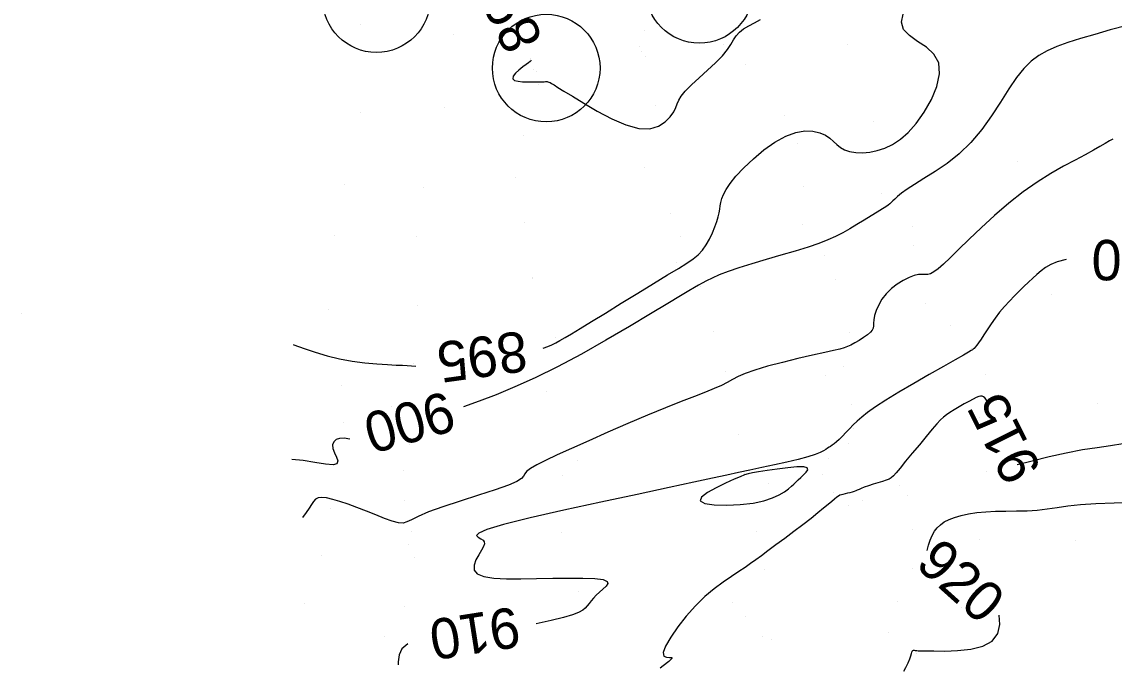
# Model space of a CAD drawing. Extents: x 400243 to 403697, y 4403637 to 4408083.
# Drawn here: x 402504.4 to 402707.4, y 4405858.2 to 4405978.9 of the extents above; entities that cross this region are included whole.
import ezdxf

# ---------------------------------------------------------------- set-up
doc = ezdxf.new("R2010")
doc.units = 0
for name, color, linetype in [('HH_DiS', 7, 'Continuous'), ('HH_IC', 7, 'Continuous'), ('SNR_ONAMA', 7, 'Continuous')]:
    doc.layers.add(name, color=color, linetype=linetype)

msp = doc.modelspace()

# ---------------------------------------------------------------- linework, layer by layer
at = {"layer": 'HH_DiS'}
msp.add_line((402504.4, 4405924.73), (402504.4, 4405924.73), dxfattribs=at)
at = {"layer": 'HH_IC'}
for p, q in [((402567.41, 4405978.32), (402567.41, 4405978.32)), ((402599.72, 4405977.73), (402599.72, 4405977.73)), ((402620.1, 4405977.21), (402620.1, 4405977.21)), ((402584.66, 4405976.5), (402584.66, 4405976.5)), ((402619.26, 4405974.35), (402619.26, 4405974.35)), ((402619.63, 4405973.41), (402619.63, 4405973.41)), ((402634.75, 4405974.66), (402634.75, 4405974.66)), ((402657.86, 4405974.74), (402657.86, 4405974.74)), ((402598.88, 4405972), (402598.88, 4405972)), ((402620.2, 4405972.39), (402620.2, 4405972.39)), ((402638.88, 4405970.91), (402638.88, 4405970.91)), ((402599.47, 4405970.08), (402599.47, 4405970.08)), ((402600.09, 4405969.61), (402600.09, 4405969.61)), ((402600.34, 4405967.28), (402600.34, 4405967.28)), ((402582.89, 4405963.02), (402582.89, 4405963.02)), ((402622.14, 4405963.27), (402622.14, 4405963.27)), ((402567.32, 4405961.95), (402567.32, 4405961.95)), ((402646.13, 4405961.54), (402646.13, 4405961.54)), ((402662.57, 4405960.36), (402662.57, 4405960.36)), ((402597.54, 4405957.69), (402597.54, 4405957.69)), ((402648.47, 4405956.34), (402648.47, 4405956.34)), ((402689.48, 4405952.9), (402689.48, 4405952.9)), ((402620.08, 4405951.86), (402620.08, 4405951.86)), ((402564.33, 4405948.7), (402564.33, 4405948.7)), ((402596.16, 4405950), (402596.16, 4405950)), ((402579.05, 4405948.12), (402579.05, 4405948.12)), ((402649.67, 4405948.24), (402649.67, 4405948.24)), ((402664.22, 4405946.92), (402664.22, 4405946.92)), ((402624.85, 4405943.23), (402624.85, 4405943.23)), ((402597.74, 4405941.59), (402597.74, 4405941.59)), ((402649.48, 4405941.23), (402649.48, 4405941.23)), ((402669.95, 4405940.82), (402669.95, 4405940.82)), ((402562.58, 4405939.24), (402562.58, 4405939.24)), ((402577.72, 4405938.95), (402577.72, 4405938.95)), ((402626.84, 4405939.04), (402626.84, 4405939.04)), ((402670.1, 4405937.33), (402670.1, 4405937.33)), ((402653.55, 4405935.46), (402653.55, 4405935.46)), ((402626.13, 4405934.15), (402626.13, 4405934.15)), ((402599.3, 4405931.25), (402599.3, 4405931.25)), ((402599.31, 4405931.33), (402599.31, 4405931.33)), ((402655.68, 4405931.05), (402655.68, 4405931.05)), ((402630.43, 4405929.66), (402630.43, 4405929.66)), ((402695.72, 4405928.13), (402695.72, 4405928.13)), ((402578.01, 4405926.16), (402578.01, 4405926.16)), ((402672.32, 4405926.46), (402672.32, 4405926.46)), ((402561.38, 4405925.37), (402561.38, 4405925.37)), ((402676.98, 4405922.5), (402676.98, 4405922.5)), ((402603.54, 4405920.14), (402603.54, 4405920.14)), ((402632.92, 4405921.41), (402632.92, 4405921.41)), ((402658.21, 4405921.16), (402658.21, 4405921.16)), ((402680.86, 4405918.12), (402680.86, 4405918.12)), ((402577.21, 4405915.37), (402577.21, 4405915.37)), ((402635.07, 4405913.98), (402635.07, 4405913.98)), ((402657.08, 4405914.74), (402657.08, 4405914.74)), ((402653.68, 4405913.16), (402653.68, 4405913.16)), ((402683.55, 4405913.25), (402683.55, 4405913.25)), ((402563.78, 4405911.26), (402563.78, 4405911.26)), ((402601.94, 4405910.25), (402601.94, 4405910.25)), ((402685.86, 4405909.63), (402685.86, 4405909.63)), ((402704.22, 4405907.86), (402704.22, 4405907.86)), ((402573.05, 4405907.42), (402573.05, 4405907.42)), ((402658.56, 4405907.74), (402658.56, 4405907.74)), ((402564.26, 4405904.35), (402564.26, 4405904.35)), ((402573.53, 4405904.11), (402573.53, 4405904.11)), ((402682.44, 4405905.31), (402682.44, 4405905.31)), ((402637.59, 4405902.25), (402637.59, 4405902.25)), ((402658.97, 4405903.37), (402658.97, 4405903.37)), ((402576.46, 4405900.32), (402576.46, 4405900.32)), ((402657.93, 4405900.57), (402657.93, 4405900.57)), ((402654.32, 4405897.76), (402654.32, 4405897.76)), ((402607.61, 4405897.36), (402607.61, 4405897.36)), ((402575.39, 4405895.54), (402575.39, 4405895.54)), ((402604.91, 4405894.63), (402604.91, 4405894.63)), ((402638.71, 4405894.99), (402638.71, 4405894.99)), ((402653.26, 4405894.7), (402653.26, 4405894.7)), ((402683.59, 4405895.37), (402683.59, 4405895.37)), ((402643.21, 4405893.04), (402643.21, 4405893.04)), ((402667.46, 4405892.72), (402667.46, 4405892.72)), ((402575.54, 4405889.88), (402575.54, 4405889.88)), ((402655.18, 4405891.41), (402655.18, 4405891.41)), ((402660.66, 4405890), (402660.66, 4405890)), ((402668.94, 4405890.8), (402668.94, 4405890.8)), ((402561.84, 4405888.47), (402561.84, 4405888.47)), ((402657.98, 4405888.93), (402657.98, 4405888.93)), ((402576.83, 4405884.1), (402576.83, 4405884.1)), ((402604.75, 4405883.93), (402604.75, 4405883.93)), ((402640.98, 4405884.13), (402640.98, 4405884.13)), ((402669.84, 4405884.49), (402669.84, 4405884.49)), ((402576.25, 4405881.73), (402576.25, 4405881.73)), ((402682.37, 4405882.6), (402682.37, 4405882.6)), ((402700.26, 4405882.55), (402700.26, 4405882.55)), ((402560.17, 4405879.63), (402560.17, 4405879.63)), ((402577.32, 4405879.31), (402577.32, 4405879.31)), ((402669.98, 4405877.33), (402669.98, 4405877.33)), ((402642.42, 4405877.11), (402642.42, 4405877.11)), ((402677.56, 4405874.28), (402677.56, 4405874.28)), ((402607.77, 4405873.07), (402607.77, 4405873.07)), ((402556.95, 4405870.74), (402556.95, 4405870.74)), ((402575.45, 4405870.23), (402575.45, 4405870.23)), ((402636.42, 4405870.91), (402636.42, 4405870.91)), ((402667.2, 4405871.12), (402667.2, 4405871.12)), ((402679, 4405870.04), (402679, 4405870.04)), ((402638.86, 4405868.37), (402638.86, 4405868.37)), ((402665.36, 4405865.47), (402665.36, 4405865.47)), ((402571.72, 4405864.59), (402571.72, 4405864.59)), ((402641.96, 4405864.69), (402641.96, 4405864.69)), ((402643.76, 4405864.07), (402643.76, 4405864.07)), ((402670.74, 4405861.47), (402670.74, 4405861.47))]:
    msp.add_line(p, q, dxfattribs=at)
for points in [[(402599.06, 4405971.76), (402598.99, 4405971.63), (402598.84, 4405971.49), (402598.56, 4405971.28), (402598.11, 4405970.96), (402597.48, 4405970.49), (402596.78, 4405969.92), (402596.14, 4405969.32), (402595.71, 4405968.76), (402595.61, 4405968.3), (402595.94, 4405967.99), (402596.6, 4405967.82), (402597.45, 4405967.75), (402598.33, 4405967.74), (402599.1, 4405967.75), (402599.65, 4405967.75), (402600.01, 4405967.75), (402600.23, 4405967.74), (402600.39, 4405967.73), (402600.54, 4405967.73), (402600.74, 4405967.73), (402600.97, 4405967.73), (402601.23, 4405967.74), (402601.47, 4405967.75), (402601.69, 4405967.76), (402601.87, 4405967.77), (402602.03, 4405967.76), (402602.17, 4405967.73), (402602.34, 4405967.67), (402602.56, 4405967.57), (402602.85, 4405967.42), (402603.3, 4405967.15), (402604.03, 4405966.7), (402605.14, 4405966.02), (402606.73, 4405965.03), (402608.84, 4405963.73), (402611.33, 4405962.27), (402614.01, 4405960.87), (402616.65, 4405959.73), (402619.06, 4405959.06), (402621.09, 4405959.02), (402622.71, 4405959.48), (402623.97, 4405960.27), (402624.9, 4405961.22), (402625.53, 4405962.16), (402625.92, 4405962.96), (402626.18, 4405963.65), (402626.47, 4405964.33), (402626.93, 4405965.09), (402627.69, 4405966.01), (402628.84, 4405967.16), (402630.28, 4405968.48), (402631.83, 4405969.88), (402633.32, 4405971.27), (402634.59, 4405972.57), (402635.51, 4405973.71), (402636.16, 4405974.68), (402636.67, 4405975.53), (402637.16, 4405976.28), (402637.75, 4405976.94), (402638.53, 4405977.55), (402639.48, 4405978.13), (402640.54, 4405978.71), (402641.67, 4405979.31)], [(402601.27, 4405918.2), (402602.14, 4405918.54), (402602.89, 4405918.87), (402603.61, 4405919.22), (402604.39, 4405919.64), (402605.34, 4405920.18), (402606.56, 4405920.91), (402608.15, 4405921.88), (402610.23, 4405923.16), (402612.83, 4405924.76), (402615.77, 4405926.58), (402618.84, 4405928.47), (402621.78, 4405930.27), (402624.36, 4405931.84), (402626.41, 4405933.06), (402627.98, 4405934.02), (402629.17, 4405934.83), (402630.1, 4405935.59), (402630.86, 4405936.42), (402631.56, 4405937.41), (402632.18, 4405938.51), (402632.73, 4405939.65), (402633.19, 4405940.76), (402633.55, 4405941.78), (402633.8, 4405942.65), (402633.97, 4405943.39), (402634.08, 4405944.05), (402634.18, 4405944.68), (402634.3, 4405945.32), (402634.47, 4405946.02), (402634.76, 4405946.81), (402635.25, 4405947.73), (402636, 4405948.84), (402637.1, 4405950.18), (402638.57, 4405951.74), (402640.35, 4405953.42), (402642.31, 4405955.06), (402644.34, 4405956.52), (402646.34, 4405957.64), (402648.2, 4405958.32), (402649.88, 4405958.59), (402651.38, 4405958.54), (402652.66, 4405958.25), (402653.72, 4405957.79), (402654.56, 4405957.24), (402655.24, 4405956.66), (402655.85, 4405956.08), (402656.5, 4405955.54), (402657.27, 4405955.09), (402658.22, 4405954.77), (402659.35, 4405954.59), (402660.61, 4405954.55), (402661.96, 4405954.67), (402663.36, 4405954.94), (402664.78, 4405955.4), (402666.21, 4405956.08), (402667.66, 4405957.04), (402669.12, 4405958.33), (402670.6, 4405960.01), (402672.08, 4405962.09), (402673.41, 4405964.44), (402674.42, 4405966.87), (402674.94, 4405969.19), (402674.8, 4405971.23), (402673.9, 4405972.85), (402672.48, 4405974.15), (402670.86, 4405975.25), (402669.35, 4405976.31), (402668.26, 4405977.46), (402667.87, 4405978.81), (402668.17, 4405980.32)], [(402709.77, 4405978.22), (402706.64, 4405977.36), (402703.76, 4405976.54), (402701.14, 4405975.77), (402698.79, 4405975.01), (402696.72, 4405974.27), (402694.93, 4405973.5), (402693.37, 4405972.63), (402691.95, 4405971.57), (402690.59, 4405970.23), (402689.24, 4405968.52), (402687.81, 4405966.4), (402686.27, 4405963.97), (402684.6, 4405961.4), (402682.77, 4405958.84), (402680.77, 4405956.45), (402678.58, 4405954.36), (402676.32, 4405952.57), (402674.09, 4405951.04), (402672.03, 4405949.75), (402670.27, 4405948.67), (402668.89, 4405947.76), (402667.86, 4405947.02), (402667.12, 4405946.42), (402666.6, 4405945.94), (402666.24, 4405945.58), (402665.97, 4405945.31), (402665.72, 4405945.07), (402665.41, 4405944.83), (402664.96, 4405944.52), (402664.3, 4405944.1), (402663.37, 4405943.51), (402662.22, 4405942.8), (402660.94, 4405942.02), (402659.58, 4405941.21), (402658.23, 4405940.42), (402656.94, 4405939.69), (402655.62, 4405939.01), (402654.17, 4405938.35), (402652.5, 4405937.69), (402650.5, 4405937), (402648.11, 4405936.26), (402645.46, 4405935.49), (402642.71, 4405934.7), (402640.06, 4405933.93), (402637.65, 4405933.18), (402635.64, 4405932.48), (402634.01, 4405931.84), (402632.69, 4405931.26), (402631.65, 4405930.75), (402630.83, 4405930.31), (402630.14, 4405929.93), (402629.39, 4405929.5), (402628.34, 4405928.88), (402626.78, 4405927.93), (402624.46, 4405926.52), (402621.24, 4405924.58), (402617.31, 4405922.24), (402612.94, 4405919.69), (402608.39, 4405917.13), (402603.93, 4405914.76), (402599.79, 4405912.72), (402595.99, 4405911.01), (402592.52, 4405909.58), (402589.36, 4405908.36), (402586.48, 4405907.31)], [(402707.11, 4405957.08), (402706.49, 4405956.73), (402705.72, 4405956.27), (402704.74, 4405955.69), (402703.51, 4405955), (402701.98, 4405954.17), (402700.12, 4405953.19), (402697.97, 4405952.04), (402695.6, 4405950.69), (402693.07, 4405949.1), (402690.44, 4405947.26), (402687.78, 4405945.15), (402685.17, 4405942.89), (402682.69, 4405940.61), (402680.43, 4405938.46), (402678.48, 4405936.56), (402676.9, 4405935.02), (402675.65, 4405933.84), (402674.67, 4405932.99), (402673.9, 4405932.41), (402673.27, 4405932.07), (402672.73, 4405931.92), (402672.21, 4405931.9), (402671.66, 4405931.92), (402671.02, 4405931.89), (402670.24, 4405931.73), (402669.28, 4405931.37), (402668.2, 4405930.83), (402667.07, 4405930.13), (402665.99, 4405929.29), (402665.02, 4405928.35), (402664.23, 4405927.32), (402663.62, 4405926.26), (402663.17, 4405925.23), (402662.87, 4405924.29), (402662.71, 4405923.48), (402662.65, 4405922.85), (402662.64, 4405922.36), (402662.6, 4405921.95), (402662.44, 4405921.57), (402662.11, 4405921.17), (402661.54, 4405920.69), (402660.81, 4405920.18), (402659.98, 4405919.66), (402659.16, 4405919.19), (402658.42, 4405918.8), (402657.8, 4405918.51), (402657.19, 4405918.29), (402656.39, 4405918.07), (402655.25, 4405917.81), (402653.59, 4405917.44), (402651.3, 4405916.92), (402648.59, 4405916.29), (402645.72, 4405915.59), (402642.97, 4405914.86), (402640.6, 4405914.16), (402638.81, 4405913.53), (402637.48, 4405912.94), (402636.43, 4405912.39), (402635.47, 4405911.85), (402634.41, 4405911.29), (402633.08, 4405910.71), (402631.42, 4405910.05), (402629.38, 4405909.26), (402626.93, 4405908.31), (402624.02, 4405907.15), (402620.66, 4405905.76), (402617.02, 4405904.21), (402613.31, 4405902.6), (402609.74, 4405901.03), (402606.53, 4405899.6), (402603.85, 4405898.38), (402601.71, 4405897.37), (402600.08, 4405896.54), (402598.92, 4405895.86), (402598.2, 4405895.31), (402597.85, 4405894.86), (402597.63, 4405894.44), (402597.24, 4405894), (402596.41, 4405893.47), (402594.84, 4405892.79), (402592.36, 4405891.91), (402589.24, 4405890.89), (402585.88, 4405889.82), (402582.66, 4405888.75), (402579.96, 4405887.78), (402578.06, 4405886.96), (402576.81, 4405886.34), (402575.96, 4405885.92), (402575.24, 4405885.73), (402574.4, 4405885.78), (402573.24, 4405886.09), (402571.79, 4405886.6), (402570.15, 4405887.23), (402568.42, 4405887.92), (402566.68, 4405888.6), (402565.04, 4405889.21), (402563.52, 4405889.73), (402562.18, 4405890.12), (402561.03, 4405890.38), (402560.12, 4405890.47), (402559.45, 4405890.39), (402558.97, 4405890.14), (402558.6, 4405889.74), (402558.24, 4405889.18), (402557.81, 4405888.49), (402557.25, 4405887.68), (402556.58, 4405886.75)], [(402698.47, 4405934.68), (402696.78, 4405934.27), (402695.58, 4405933.77), (402694.65, 4405933.2), (402693.82, 4405932.58), (402693.02, 4405931.92), (402692.24, 4405931.22), (402691.45, 4405930.47), (402690.62, 4405929.68), (402689.74, 4405928.83), (402688.83, 4405927.94), (402687.9, 4405926.99), (402686.99, 4405925.99), (402686.1, 4405924.94), (402685.27, 4405923.83), (402684.5, 4405922.73), (402683.8, 4405921.66), (402683.18, 4405920.69), (402682.64, 4405919.87), (402682.2, 4405919.23), (402681.85, 4405918.76), (402681.57, 4405918.42), (402681.36, 4405918.19), (402681.2, 4405918.04), (402681.06, 4405917.93), (402680.81, 4405917.77), (402680.3, 4405917.47), (402679.36, 4405916.94), (402677.84, 4405916.08), (402675.66, 4405914.84), (402673.01, 4405913.33), (402670.16, 4405911.68), (402667.37, 4405910.04), (402664.92, 4405908.54), (402663, 4405907.3), (402661.56, 4405906.28), (402660.47, 4405905.42), (402659.63, 4405904.67), (402658.9, 4405903.96), (402658.2, 4405903.24), (402657.51, 4405902.53), (402656.87, 4405901.86), (402656.28, 4405901.27), (402655.77, 4405900.79), (402655.34, 4405900.43), (402654.99, 4405900.17), (402654.69, 4405899.97), (402654.41, 4405899.8), (402654.13, 4405899.62), (402653.81, 4405899.4), (402653.38, 4405899.14), (402652.74, 4405898.82), (402651.8, 4405898.45), (402650.47, 4405898.03), (402648.69, 4405897.56), (402646.58, 4405897.06), (402644.27, 4405896.54), (402641.92, 4405896.03), (402639.68, 4405895.55), (402637.59, 4405895.09), (402635.4, 4405894.62), (402632.75, 4405894.04), (402629.29, 4405893.3), (402624.68, 4405892.32), (402618.72, 4405891.05), (402611.97, 4405889.6), (402605.11, 4405888.09), (402598.86, 4405886.67), (402593.93, 4405885.44), (402590.82, 4405884.52), (402589.29, 4405883.86), (402588.89, 4405883.4), (402589.17, 4405883.08), (402589.71, 4405882.82), (402590.12, 4405882.56), (402590.34, 4405882.26), (402590.36, 4405881.88), (402590.19, 4405881.37), (402589.83, 4405880.7), (402589.31, 4405879.84), (402588.79, 4405878.88), (402588.45, 4405877.9), (402588.47, 4405876.99), (402589.03, 4405876.26), (402590.27, 4405875.76), (402592.12, 4405875.48), (402594.45, 4405875.36), (402597.13, 4405875.34), (402600.05, 4405875.39), (402603.06, 4405875.45), (402605.99, 4405875.5), (402608.65, 4405875.49), (402610.86, 4405875.4), (402612.41, 4405875.21), (402613.18, 4405874.89), (402613.31, 4405874.47), (402612.98, 4405873.97), (402612.39, 4405873.42), (402611.72, 4405872.86), (402611.13, 4405872.31), (402610.63, 4405871.77), (402610.2, 4405871.26), (402609.82, 4405870.78), (402609.47, 4405870.33), (402609.11, 4405869.91), (402608.62, 4405869.51), (402607.86, 4405869.1), (402606.72, 4405868.66), (402605.05, 4405868.16), (402602.77, 4405867.59), (402599.97, 4405866.99)], [(402554.82, 4405918.9), (402554.97, 4405918.85), (402556.86, 4405918.19), (402558.91, 4405917.49), (402561.11, 4405916.82), (402563.41, 4405916.24), (402565.79, 4405915.8), (402568.14, 4405915.5), (402570.36, 4405915.29), (402572.34, 4405915.16), (402573.95, 4405915.09), (402575.14, 4405915.04), (402576.03, 4405915), (402576.8, 4405914.96), (402577.61, 4405914.88)], [(402683.97, 4405907.34), (402683.81, 4405908.14), (402683.59, 4405908.68), (402683.34, 4405909), (402683.08, 4405909.19), (402682.83, 4405909.29), (402682.56, 4405909.3), (402682.21, 4405909.22), (402681.76, 4405909.04), (402681.16, 4405908.75), (402680.38, 4405908.34), (402679.5, 4405907.85), (402678.56, 4405907.31), (402677.66, 4405906.78), (402676.87, 4405906.29), (402676.22, 4405905.86), (402675.66, 4405905.42), (402675.09, 4405904.88), (402674.43, 4405904.15), (402673.57, 4405903.15), (402672.45, 4405901.83), (402671.18, 4405900.29), (402669.86, 4405898.69), (402668.63, 4405897.2), (402667.61, 4405895.95), (402666.87, 4405895.06), (402666.36, 4405894.48), (402665.96, 4405894.13), (402665.55, 4405893.9), (402665.03, 4405893.71), (402664.32, 4405893.47), (402663.47, 4405893.2), (402662.57, 4405892.92), (402661.7, 4405892.64), (402660.95, 4405892.38), (402660.39, 4405892.16), (402659.97, 4405891.98), (402659.65, 4405891.83), (402659.36, 4405891.69), (402659.04, 4405891.57), (402658.67, 4405891.46), (402658.24, 4405891.35), (402657.8, 4405891.25), (402657.37, 4405891.15), (402656.99, 4405891.06), (402656.69, 4405890.98), (402656.42, 4405890.88), (402656.15, 4405890.73), (402655.83, 4405890.51), (402655.44, 4405890.19), (402654.92, 4405889.75), (402654.24, 4405889.18), (402653.39, 4405888.47), (402652.34, 4405887.6), (402651.05, 4405886.58), (402649.54, 4405885.41), (402647.87, 4405884.15), (402646.17, 4405882.87), (402644.52, 4405881.65), (402643.05, 4405880.56), (402641.82, 4405879.65), (402640.77, 4405878.88), (402639.79, 4405878.18), (402638.78, 4405877.48), (402637.63, 4405876.71), (402636.28, 4405875.81), (402634.74, 4405874.75), (402633.08, 4405873.5), (402631.33, 4405872.05), (402629.57, 4405870.35), (402627.85, 4405868.43), (402626.28, 4405866.42), (402624.97, 4405864.51), (402624.03, 4405862.86), (402623.6, 4405861.66), (402623.71, 4405861.01), (402624.17, 4405860.78), (402624.74, 4405860.76), (402625.16, 4405860.75), (402625.18, 4405860.55), (402624.61, 4405860), (402623.58, 4405859.19), (402623.03, 4405858.77)], [(402565.36, 4405901.29), (402564.31, 4405901.47), (402563.44, 4405901.45), (402562.78, 4405901.23), (402562.35, 4405900.83), (402562.15, 4405900.27), (402562.22, 4405899.58), (402562.52, 4405898.79), (402562.89, 4405897.99), (402563.11, 4405897.27), (402562.96, 4405896.75), (402562.25, 4405896.53), (402560.82, 4405896.65), (402558.87, 4405896.99), (402556.65, 4405897.35), (402554.55, 4405897.53)], [(402708.96, 4405900.46), (402706.68, 4405900.06), (402704.23, 4405899.72), (402701.5, 4405899.31), (402698.46, 4405898.73), (402695.27, 4405898.01), (402692.17, 4405897.25), (402689.36, 4405896.53)], [(402630.47, 4405889.83), (402631.34, 4405889.35), (402633.08, 4405889.09), (402635.38, 4405889.03), (402637.88, 4405889.15), (402640.27, 4405889.44), (402642.27, 4405889.86), (402643.87, 4405890.39), (402645.13, 4405890.96), (402646.1, 4405891.55), (402646.85, 4405892.09), (402647.42, 4405892.57), (402647.87, 4405892.98), (402648.27, 4405893.38), (402648.67, 4405893.77), (402649.13, 4405894.21), (402649.67, 4405894.69), (402650.16, 4405895.18), (402650.44, 4405895.63), (402650.35, 4405895.98), (402649.72, 4405896.17), (402648.44, 4405896.16), (402646.71, 4405896), (402644.78, 4405895.75), (402642.89, 4405895.47), (402641.29, 4405895.22), (402640.17, 4405895.03), (402639.37, 4405894.86), (402638.68, 4405894.66), (402637.88, 4405894.34), (402636.75, 4405893.85), (402635.18, 4405893.14), (402633.41, 4405892.29), (402631.81, 4405891.39), (402630.71, 4405890.54), (402630.47, 4405889.83)], [(402672.65, 4405880.63), (402672.9, 4405881.59), (402673.21, 4405882.55), (402673.57, 4405883.43), (402673.99, 4405884.2), (402674.49, 4405884.86), (402675.09, 4405885.42), (402675.81, 4405885.92), (402676.69, 4405886.37), (402677.73, 4405886.77), (402678.94, 4405887.13), (402680.31, 4405887.43), (402681.84, 4405887.67), (402683.52, 4405887.83), (402685.35, 4405887.91), (402687.27, 4405887.95), (402689.23, 4405887.97), (402691.19, 4405888.02), (402693.09, 4405888.14), (402694.91, 4405888.35), (402696.76, 4405888.61), (402698.79, 4405888.91), (402701.15, 4405889.18), (402703.98, 4405889.38), (402707.36, 4405889.51), (402711.11, 4405889.6)], [(402668.29, 4405858.2), (402668.65, 4405858.85), (402669.1, 4405859.77), (402669.41, 4405860.5), (402669.61, 4405861.06), (402669.72, 4405861.46), (402669.8, 4405861.74), (402669.87, 4405861.91), (402669.96, 4405862.02), (402670.08, 4405862.07), (402670.22, 4405862.08), (402670.37, 4405862.06), (402670.52, 4405862.04), (402670.69, 4405862.02), (402670.98, 4405862), (402671.53, 4405861.99), (402672.46, 4405861.97), (402673.9, 4405861.95), (402675.91, 4405861.94), (402678.29, 4405862.02), (402680.73, 4405862.29), (402682.97, 4405862.85), (402684.71, 4405863.8), (402685.75, 4405865.19), (402686.14, 4405866.86), (402686.03, 4405868.63)], [(402576.12, 4405863.25), (402575.03, 4405862.36), (402574.5, 4405861.23), (402574.33, 4405859.91), (402574.33, 4405859.39)]]:
    msp.add_lwpolyline(points, dxfattribs=at)
at = {"layer": 'SNR_ONAMA'}
for centre in [(402570.3, 4405983.18), (402630.31, 4405984.91), (402601.84, 4405970.28)]:
    msp.add_circle(centre, 10, dxfattribs=at)

# ---------------------------------------------------------------- texts
at = {"layer": 'HH_IC'}
for s, rotation, p in [('890', 115.7576, (402601.37, 4405975.59)), ('910', 179.355, (402719.96, 4405938.19)), ('895', 187.9863, (402597.74, 4405921.49)), ('900', 195.8945, (402583.46, 4405910.34)), ('915', 116.5066, (402694, 4405895.64)), ('920', 318.1084, (402670.21, 4405877.79)), ('910', 188.9192, (402596.26, 4405870.21))]:
    msp.add_text(s, height=7.5, rotation=rotation, dxfattribs=at).set_placement(p)

doc.saveas('drawing.dxf')
